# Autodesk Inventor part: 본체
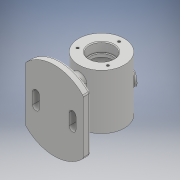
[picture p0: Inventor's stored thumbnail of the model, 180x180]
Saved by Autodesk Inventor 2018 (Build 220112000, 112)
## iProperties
Created: 2022-02
Part Number: 본체
Material: Generic
Document SubType Name: Modeling
Designer: 1class 2
Density: 1 g/cm^3
Appearance: Default
Author: 1class 2
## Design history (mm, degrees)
sketch "스케치1"
  geometry: L1 (38, 54.198)-(-38, 54.198); L2 (-38, 54.198)-(-38, 35.496); L3 (-38, -54.198)-(38, -54.198); L4 (38, -54.198)-(38, -35.496); L5 (38, 54.198)-(-38, -54.198); L6 (-38, 54.198)-(38, -54.198); L7 (38, 35.496)-(38, 54.198); L8 (38, -35.496)-(38, 35.496); L9 (-38, 35.496)-(-38, -35.496); L10 (-38, -35.496)-(-38, -54.198); L11 (0, 19)-(0, -19); L12 (-7, 19)-(-7, -19); L13 (7, -19)-(7, 19); L14 (24, 7.5)-(24, -7.5); L15 (19.5, 7.5)-(19.5, -7.5); L16 (28.5, -7.5)-(28.5, 7.5); L17 (-24, 7.5)-(-24, -7.5); L18 (-28.5, 7.5)-(-28.5, -7.5); L19 (-19.5, -7.5)-(-19.5, 7.5); C1 r 42.5 at (0, 0); A1 r 52 centre (0, 0) between (-38, -35.496) and (38, -35.496); A2 r 52 centre (0, 0) between (-38, 35.496) and (-38, -35.496); A3 r 52 centre (0, 0) between (38, -35.496) and (38, 35.496); A4 r 52 centre (0, 0) between (38, 35.496) and (-38, 35.496); A5 r 7 centre (0, 19) between (7, 19) and (-7, 19); A6 r 7 centre (0, -19) between (-7, -19) and (7, -19); A7 r 4.5 centre (24, 7.5) between (28.5, 7.5) and (19.5, 7.5); A8 r 4.5 centre (24, -7.5) between (19.5, -7.5) and (28.5, -7.5); A9 r 4.5 centre (-24, 7.5) between (-19.5, 7.5) and (-28.5, 7.5); A10 r 4.5 centre (-24, -7.5) between (-28.5, -7.5) and (-19.5, -7.5); 6 further points
  constraints: 44 end point, 20 point on circle, 14 parallel, 12 tangent, 11 centre point, 7 midpoint, 4 coincident, 3 perpendicular, 1 horizontal, 1 horizontal alignment, 1 point on line, 1 vertical, 1 vertical alignment
  dimensions: "d0" = 104 diameter of A1; "d1" = 76 distance of L3.end L3.start; "d2" = 18.70114 distance of L3.end L4.end; "d3" = 38 distance of L11.start L11.end; "d4" = 14 diameter of A6; "d5" = 15 distance of L14.start L14.end; "d6" = 9 diameter of A8; "d7" = 15 distance of L17.start L17.end; "d8" = 9 diameter of A10; "d9" = 48 distance of point (-24, 0) point (24, 0); "d10" = 24 distance of A1.centre point (24, 0); "d11" = 24 distance of point (0, 0) point (-24, 0); "d53" = 85 diameter of C1
extrude "돌출1" new body sketch "스케치1" distance "d12" = 10; taper "d13" = 0 deg
extrude "돌출2" join sketch "스케치1" distance "d14" = 40; taper "d15" = 0 deg
sketch "스케치2"
  geometry: L1 (38, 0)-(-38, 0) reference; C1 r 30 at (0, 62); 1 further point
  constraints: 1 centre point, 1 vertical alignment
  dimensions: "d16" = 60 diameter of C1; "d17" = 62 vertical distance of C1.centre L1.start
extrude "돌출3" join sketch "스케치2" stored distance "d18" = 72; taper "d19" = 0 deg
sketch "스케치6"
  geometry: L1 (0, 62)-(16.5, 90.579); L2 (0, 62)-(0, 92); L3 (19.476, 87.734)-(15.621, 81.056); L4 (22.941, 85.734)-(18.388, 77.849); L5 (19.476, 87.734)-(22.941, 85.734); L6 (15.621, 81.056)-(18.388, 77.849); 1 further point
  constraints: 12 end point, 1 parallel, 1 vertical
  dimensions: "d55" = 33 distance of L1.start L1.end; "d56" = 30 deg angle of L2 L1; "d58" = 8 diameter of L3 L1; "d60" = 16 diameter of L4 L1; "d61" = 3.46448 horizontal distance of L3.start L4.start
revolve "회전2" stored, may be unused: angle "d62" = 90 deg
sketch "스케치3"
  geometry: L1 (92, -36)-(92, 36) reference; L2 (92, 36)-(32, 36) reference; L3 (32, -36)-(92, -36) reference; L4 (32, -36)-(32, 36) reference; L5 (78, 36)-(78, 24.3); L6 (77.7, 24)-(76, 24); L7 (76, 24)-(76, 20); L8 (76, 20)-(87, 20); L9 (87, 20)-(87, -20); L10 (87, -20)-(76, -20); L11 (76, -20)-(76, -24); L12 (76, -24)-(77.7, -24); L13 (78, -24.3)-(78, -36); L14 (62, 36)-(62, -36); A1 r 0.3 centre (77.7, 24.3) between (77.7, 24) and (78, 24.3); A2 r 0.3 centre (77.7, -24.3) between (78, -24.3) and (77.7, -24); 3 further points
  constraints: 20 end point, 10 point on line, 6 perpendicular, 4 point on circle, 4 tangent, 2 centre point, 2 midpoint, 1 equal radius, 1 vertical
  dimensions: "d20" = 50 diameter of L9 L14; "d21" = 32 diameter of L5 L14; "d22" = 28 diameter of L7 L14; "d23" = 40 distance of L8.end L9.end; "d24" = 12 distance of L5.start point (78, 24); "d25" = 12 distance of point (78, -24) L13.end; "d26" = 4 distance of L6.end L7.end; "d28" = 0.3 radius of A1
revolve "회전1" sketch "스케치3" stored, may be unused: angle "d27" = 90 deg
sketch "스케치4" dims "d29" = 46
  geometry: C1 r 30 at (0, 0) reference; 5 further points
  constraints: 2 coincident, 2 vertical alignment, 6 other
  dimensions: "d32" = 360 deg dimension on point (0, 0) point (0, 23) (derived)
hole "구멍1" sketch "스케치4" at (0, 23), (-19.919, -11.5), (19.919, -11.5) diameter "d34" = 3.242; stored, may be unused: countersink angle "d38" = 90 deg, drill point angle "d40" = 118 deg; dims "d35" = 8, "d36" = 4, "d37" = 2, "d39" = 10
sketch "스케치5"
  geometry: C1 r 16 at (0, 0) reference; C2 r 30 at (0, 0) reference; C3 r 23 at (0, 0); C4 r 1.621 at (0, 23) reference; 4 further points
  constraints: 2 coincident, 1 centre point, 1 vertical alignment, 4 other
  dimensions: "d41" = 46 diameter of C3; "d44" = 360 deg dimension on C3.centre point (0, 23) (derived)
hole "구멍2" sketch "스케치5" at (0, 23), (-19.919, -11.5), (19.919, -11.5) diameter "d46" = 3.242; stored, may be unused: countersink angle "d50" = 90 deg, drill point angle "d52" = 118 deg; dims "d47" = 8, "d48" = 4, "d49" = 2, "d51" = 10
sketch "스케치8"
  geometry: 1 further point
sketch "스케치9"
  geometry: C1 r 42.5 at (0, 0); 1 further point
  constraints: 1 centre point, 1 coincident, 1 other
  dimensions: "d63" = 85 diameter of C1
feature "엠보싱1" sketch "스케치9" dims "d64" = 0.5, "d65" = 0
fillet "모깎기1" dims "d66" = 3
fillet "모깎기2" dims "d67" = 3
chamfer "모따기1" distance "d69" = 1; stored, may be unused: second distance "d70" = 2, angle "d71" = 45 deg
sketch "스케치10"
  geometry: L1 (12.548, 91.734)-(19.476, 87.734) reference; L2 (16.012, 89.734)-(19.476, 87.734); L3 (19.476, 87.734)-(15.55, 80.933); L4 (15.55, 80.933)-(12.086, 82.933); L5 (12.086, 82.933)-(16.012, 89.734); 1 further point
  constraints: 8 end point, 3 perpendicular, 1 collinear, 1 midpoint
revolve "회전3" sketch "스케치10" stored, may be unused: angle "d72" = 90 deg
fillet "모깎기4" dims "d73" = 1
node "솔리드1"
node "투영된 루프1"
